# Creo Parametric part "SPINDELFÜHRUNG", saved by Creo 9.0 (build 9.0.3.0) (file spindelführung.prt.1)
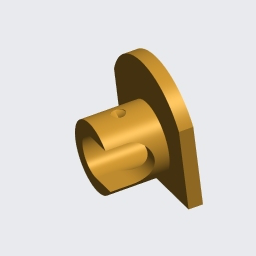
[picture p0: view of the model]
Units: millimeter Kilogram Sec (mmKs); MM, KILOGRAM, SECS
Materials in the file: STAHL

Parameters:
  WERKSTOFF = "Stahl"
  ERSTELLER = "ARINDA"
  BENENNUNG = "XXX"
  TEILETYP = "K"
  PTC_MASTER_MATERIAL = "STAHL"

Other parameters: MASSE

Created from: ARINDA_STARTTEIL.PRT

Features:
  1. coordinate system
  2. datum plane "RECHTS_Y-Z"
  3. datum plane "OBEN_X-Z"
  4. datum plane "VORNE_X-Y"
  5. datum axis
  6. datum axis
  7. datum axis
  8. datum point "PNT0"
  9. extrusion "Profil 1"
  10. extruded cut "Profil 2"
  11. hole "Bohrung 1"
  12. extruded cut "Profil 3"
  13. hole "Bohrung 2"

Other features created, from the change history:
  coordinate system "CS1"

Other named items: PLATTE, ZAPFEN, NUT, FIXIERUNG, A_X, A_Y, A_Z, CS0

Layers: 01_ACHSEN, 01_ACHSEN_STD, 01_EBENEN_STD, 01_KOORDSYS_STD, 01_PUNKTE_STD, VOLUMENGEOMETRIE

Surfaces: 8 plane, 6 cylinder, 2 cone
